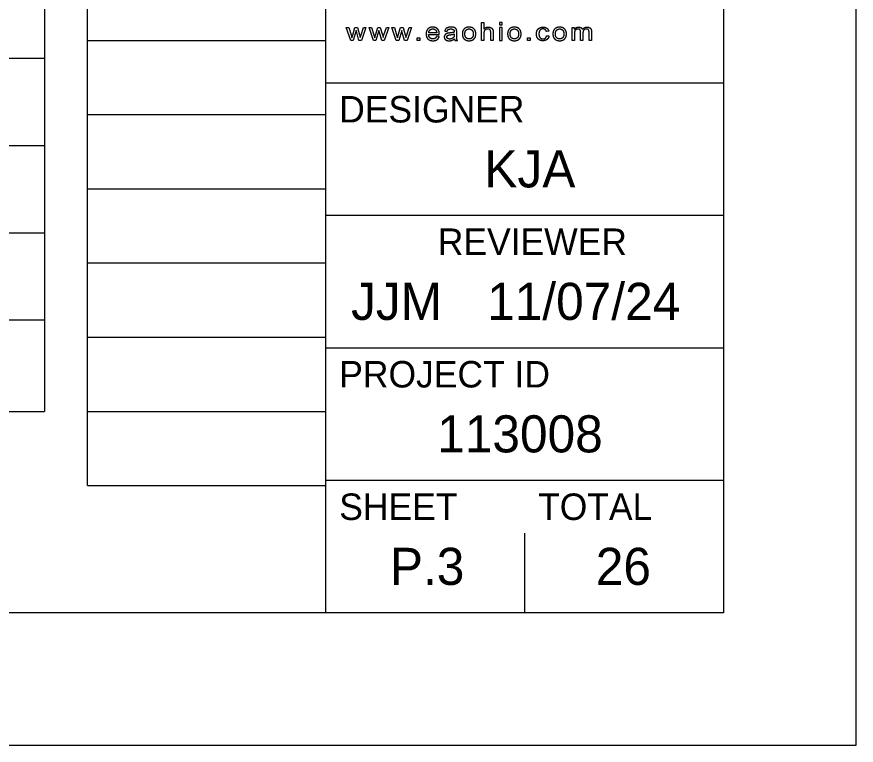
# Model space of a CAD drawing. Extents: x 0 to 34, y 0 to 22.
# Drawn here: x 30.834 to 34, y 0 to 2.749 of the extents above; entities that cross this region are included whole.
import ezdxf

# ---------------------------------------------------------------- set-up
doc = ezdxf.new("R2010")
doc.units = 0
for name, color, linetype in [('SH_Border', 7, 'Continuous'), ('SH_Cut_Line', 7, 'Continuous'), ('SH_Data', 7, 'Continuous'), ('TX_X_20', 7, 'Continuous')]:
    doc.layers.add(name, color=color, linetype=linetype)

msp = doc.modelspace()

# ---------------------------------------------------------------- linework, layer by layer
at = {"layer": 'SH_Border'}
for p, q in [((32, 0.5), (32, 21.5)), ((32, 2.5), (33.5, 2.5)), ((32, 2), (33.5, 2)), ((32, 1.5), (33.5, 1.5)), ((32, 1), (33.5, 1))]:
    msp.add_line(p, q, dxfattribs=at)
msp.add_lwpolyline([(1.5, 21.5), (33.5, 21.5), (33.5, 0.5), (1.5, 0.5)], close=True, dxfattribs=at)
at = {"layer": 'SH_Cut_Line'}
msp.add_lwpolyline([(0, 0), (34, 0), (34, 22), (0, 22)], close=True, dxfattribs=at)
at = {"layer": 'SH_Data'}
for p, q in [((31.1, 0.98), (31.1, 21.14)), ((32, 0.98), (32, 21.14)), ((30.9386, 5.2448), (30.9386, 1.2589)), ((31.1, 2.66), (32, 2.66)), ((20.5456, 2.593), (30.9386, 2.593)), ((31.1, 2.38), (32, 2.38)), ((20.5456, 2.2636), (30.9386, 2.2636)), ((31.1, 2.1), (32, 2.1)), ((20.5456, 1.9342), (30.9386, 1.9342)), ((31.1, 1.82), (32, 1.82)), ((20.5456, 1.6048), (30.9386, 1.6048)), ((31.1, 1.54), (32, 1.54)), ((20.5456, 1.2589), (30.9386, 1.2589)), ((31.1, 1.26), (32, 1.26)), ((31.1, 0.98), (32, 0.98)), ((32.75, 0.5), (32.75, 0.8)), ((32.375, 0.675), (32.375, 0.675))]:
    msp.add_line(p, q, dxfattribs=at)
at = {"layer": 'TX_X_20'}
for p, q in [((32.4477, 2.6948), (32.4567, 2.6937)), ((32.4931, 2.6802), (32.4931, 2.6913)), ((32.8402, 2.6944), (32.8313, 2.6931)), ((32.387, 2.6821), (32.4274, 2.6821)), ((32.4178, 2.6889), (32.3875, 2.6889)), ((32.4272, 2.6744), (32.4177, 2.6755)), ((32.4838, 2.6843), (32.4838, 2.6812)), ((32.4846, 2.6656), (32.4846, 2.6656)), ((32.5143, 2.6842), (32.5143, 2.6842)), ((32.5238, 2.6842), (32.5238, 2.6842)), ((32.6852, 2.6842), (32.6852, 2.6842)), ((32.6946, 2.6842), (32.6946, 2.6842)), ((32.8321, 2.6776), (32.8411, 2.6765)), ((32.856, 2.6842), (32.856, 2.6842)), ((32.8655, 2.6842), (32.8655, 2.6842)), ((32.4864, 2.6596), (32.496, 2.6596))]:
    msp.add_line(p, q, dxfattribs=at)
for points in [[(32.5955, 2.6865), (32.5955, 2.6596), (32.5863, 2.6596), (32.5863, 2.7276), (32.5955, 2.7276), (32.5955, 2.7032)], [(32.1007, 2.68), (32.1093, 2.7089), (32.1188, 2.7089), (32.1269, 2.6802), (32.1295, 2.6708), (32.1327, 2.6804), (32.142, 2.7089), (32.1509, 2.7089), (32.1339, 2.6596), (32.1244, 2.6596), (32.1158, 2.6891), (32.1137, 2.6975), (32.1027, 2.6596), (32.0931, 2.6596), (32.0766, 2.7089), (32.0861, 2.7089), (32.0947, 2.6804), (32.0979, 2.6698)], [(32.1867, 2.68), (32.1953, 2.7089), (32.2048, 2.7089), (32.2129, 2.6802), (32.2155, 2.6708), (32.2186, 2.6804), (32.228, 2.7089), (32.2369, 2.7089), (32.2199, 2.6596), (32.2104, 2.6596), (32.2018, 2.6891), (32.1997, 2.6975), (32.1886, 2.6596), (32.179, 2.6596), (32.1625, 2.7089), (32.172, 2.7089), (32.1807, 2.6804), (32.1838, 2.6698)], [(32.2726, 2.68), (32.2813, 2.7089), (32.2907, 2.7089), (32.2988, 2.6802), (32.3015, 2.6708), (32.3046, 2.6804), (32.3139, 2.7089), (32.3229, 2.7089), (32.3059, 2.6596), (32.2964, 2.6596), (32.2878, 2.6891), (32.2856, 2.6975), (32.2746, 2.6596), (32.265, 2.6596), (32.2485, 2.7089), (32.258, 2.7089), (32.2666, 2.6804), (32.2698, 2.6698)], [(32.9372, 2.6851), (32.9372, 2.6596), (32.928, 2.6596), (32.928, 2.7089), (32.9362, 2.7089), (32.9362, 2.7019)], [(32.9694, 2.6882), (32.9694, 2.6596), (32.9602, 2.6596), (32.9602, 2.6916)], [(33.0015, 2.6934), (33.0015, 2.6596), (32.9923, 2.6596), (32.9923, 2.6906)], [(32.6305, 2.6908), (32.6305, 2.6596), (32.6213, 2.6596), (32.6213, 2.6908)]]:
    msp.add_lwpolyline(points, dxfattribs=at)
for points in [[(32.655, 2.718), (32.6642, 2.718), (32.6642, 2.7276), (32.655, 2.7276)], [(32.655, 2.6596), (32.6642, 2.6596), (32.6642, 2.7089), (32.655, 2.7089)], [(32.3437, 2.6596), (32.3437, 2.669), (32.3541, 2.669), (32.3541, 2.6596)], [(32.7597, 2.6596), (32.7597, 2.669), (32.7702, 2.669), (32.7702, 2.6596)]]:
    msp.add_lwpolyline(points, close=True, dxfattribs=at)
for points in [[(32.3846, 2.7031), (32.3775, 2.6962), (32.3775, 2.6838)], [(32.4028, 2.71), (32.3916, 2.71), (32.3846, 2.7031)], [(32.3875, 2.6889), (32.388, 2.6954), (32.3923, 2.6992)], [(32.3923, 2.6992), (32.3966, 2.7031), (32.4029, 2.7031)], [(32.4206, 2.7032), (32.4137, 2.71), (32.4028, 2.71)], [(32.4029, 2.7031), (32.4099, 2.7031), (32.4143, 2.6983)], [(32.4143, 2.6983), (32.4172, 2.6951), (32.4178, 2.6889)], [(32.4275, 2.6843), (32.4275, 2.6965), (32.4206, 2.7032)], [(32.4517, 2.7032), (32.4489, 2.7), (32.4477, 2.6948)], [(32.4598, 2.7082), (32.4545, 2.7065), (32.4517, 2.7032)], [(32.4567, 2.6937), (32.4581, 2.6989), (32.4612, 2.701)], [(32.4721, 2.71), (32.4651, 2.71), (32.4598, 2.7082)], [(32.4612, 2.701), (32.4643, 2.7031), (32.4708, 2.7031)], [(32.4708, 2.7031), (32.4777, 2.7031), (32.4812, 2.7002)], [(32.4834, 2.7085), (32.479, 2.71), (32.4721, 2.71)], [(32.4812, 2.7002), (32.4838, 2.6981), (32.4838, 2.693)], [(32.4897, 2.7047), (32.4877, 2.707), (32.4834, 2.7085)], [(32.4838, 2.693), (32.4838, 2.6925), (32.4838, 2.6908)], [(32.4926, 2.699), (32.4918, 2.7025), (32.4897, 2.7047)], [(32.4931, 2.6913), (32.4931, 2.6969), (32.4926, 2.699)], [(32.5227, 2.7045), (32.5143, 2.6979), (32.5143, 2.6842)], [(32.5398, 2.71), (32.5297, 2.71), (32.5227, 2.7045)], [(32.5238, 2.6842), (32.5238, 2.6937), (32.5283, 2.6984)], [(32.5283, 2.6984), (32.5329, 2.7031), (32.5398, 2.7031)], [(32.558, 2.7033), (32.5509, 2.71), (32.5398, 2.71)], [(32.5398, 2.7031), (32.5465, 2.7031), (32.5511, 2.6983)], [(32.5511, 2.6983), (32.5556, 2.6936), (32.5556, 2.6845)], [(32.5651, 2.6849), (32.5651, 2.6966), (32.558, 2.7033)], [(32.5955, 2.7032), (32.602, 2.71), (32.6118, 2.71)], [(32.5971, 2.6956), (32.5955, 2.6923), (32.5955, 2.6865)], [(32.6022, 2.7008), (32.5986, 2.6989), (32.5971, 2.6956)], [(32.6099, 2.7028), (32.6058, 2.7028), (32.6022, 2.7008)], [(32.6183, 2.6999), (32.6153, 2.7028), (32.6099, 2.7028)], [(32.6118, 2.71), (32.6178, 2.71), (32.6222, 2.7078)], [(32.6213, 2.6908), (32.6213, 2.697), (32.6183, 2.6999)], [(32.6222, 2.7078), (32.6267, 2.7056), (32.6286, 2.7018)], [(32.6286, 2.7018), (32.6305, 2.698), (32.6305, 2.6908)], [(32.6935, 2.7045), (32.6852, 2.6979), (32.6852, 2.6842)], [(32.7106, 2.71), (32.7005, 2.71), (32.6935, 2.7045)], [(32.6946, 2.6842), (32.6946, 2.6937), (32.6992, 2.6984)], [(32.6992, 2.6984), (32.7037, 2.7031), (32.7106, 2.7031)], [(32.7288, 2.7033), (32.7218, 2.71), (32.7106, 2.71)], [(32.7106, 2.7031), (32.7174, 2.7031), (32.7219, 2.6983)], [(32.7219, 2.6983), (32.7265, 2.6936), (32.7265, 2.6845)], [(32.7359, 2.6849), (32.7359, 2.6966), (32.7288, 2.7033)], [(32.7939, 2.684), (32.7939, 2.692), (32.7968, 2.698)], [(32.7968, 2.698), (32.7997, 2.704), (32.8056, 2.707)], [(32.8077, 2.6986), (32.8033, 2.6941), (32.8033, 2.6843)], [(32.8056, 2.707), (32.8116, 2.71), (32.8186, 2.71)], [(32.8189, 2.7031), (32.812, 2.7031), (32.8077, 2.6986)], [(32.8186, 2.71), (32.8274, 2.71), (32.833, 2.7059)], [(32.8268, 2.7006), (32.8235, 2.7031), (32.8189, 2.7031)], [(32.8313, 2.6931), (32.83, 2.6981), (32.8268, 2.7006)], [(32.833, 2.7059), (32.8387, 2.7018), (32.8402, 2.6944)], [(32.8644, 2.7045), (32.856, 2.6979), (32.856, 2.6842)], [(32.8814, 2.71), (32.8714, 2.71), (32.8644, 2.7045)], [(32.8655, 2.6842), (32.8655, 2.6937), (32.87, 2.6984)], [(32.87, 2.6984), (32.8745, 2.7031), (32.8814, 2.7031)], [(32.8997, 2.7033), (32.8926, 2.71), (32.8814, 2.71)], [(32.8814, 2.7031), (32.8882, 2.7031), (32.8927, 2.6983)], [(32.8927, 2.6983), (32.8973, 2.6936), (32.8973, 2.6845)], [(32.9068, 2.6849), (32.9068, 2.6966), (32.8997, 2.7033)], [(32.9362, 2.7019), (32.9388, 2.7055), (32.943, 2.7077)], [(32.9387, 2.6954), (32.9372, 2.6918), (32.9372, 2.6851)], [(32.9434, 2.7008), (32.9401, 2.699), (32.9387, 2.6954)], [(32.943, 2.7077), (32.9472, 2.71), (32.9527, 2.71)], [(32.9506, 2.7027), (32.9467, 2.7027), (32.9434, 2.7008)], [(32.958, 2.6999), (32.9557, 2.7027), (32.9506, 2.7027)], [(32.9527, 2.71), (32.9587, 2.71), (32.9625, 2.7077)], [(32.9602, 2.6916), (32.9602, 2.6971), (32.958, 2.6999)], [(32.9625, 2.7077), (32.9664, 2.7054), (32.968, 2.7013)], [(32.968, 2.7013), (32.9744, 2.71), (32.9847, 2.71)], [(32.9732, 2.6992), (32.9694, 2.6958), (32.9694, 2.6882)], [(32.9827, 2.7027), (32.977, 2.7027), (32.9732, 2.6992)], [(32.9882, 2.7014), (32.9858, 2.7027), (32.9827, 2.7027)], [(32.9847, 2.71), (32.9928, 2.71), (32.9972, 2.7059)], [(32.9914, 2.6978), (32.9905, 2.7), (32.9882, 2.7014)], [(32.9923, 2.6906), (32.9923, 2.6956), (32.9914, 2.6978)], [(32.9972, 2.7059), (33.0015, 2.7018), (33.0015, 2.6934)], [(32.0979, 2.6698), (32.0981, 2.6706), (32.1007, 2.68)], [(32.1838, 2.6698), (32.184, 2.6706), (32.1867, 2.68)], [(32.2698, 2.6698), (32.27, 2.6706), (32.2726, 2.68)], [(32.3775, 2.6838), (32.3775, 2.6718), (32.3845, 2.6651)], [(32.3845, 2.6651), (32.3915, 2.6585), (32.4034, 2.6585)], [(32.3921, 2.6696), (32.3875, 2.6739), (32.387, 2.6821)], [(32.4034, 2.6653), (32.3966, 2.6653), (32.3921, 2.6696)], [(32.412, 2.6677), (32.4085, 2.6653), (32.4034, 2.6653)], [(32.4034, 2.6585), (32.4128, 2.6585), (32.4189, 2.6626)], [(32.4177, 2.6755), (32.4156, 2.6702), (32.412, 2.6677)], [(32.4189, 2.6626), (32.4249, 2.6668), (32.4272, 2.6744)], [(32.4274, 2.6821), (32.4275, 2.6835), (32.4275, 2.6843)], [(32.4479, 2.6792), (32.4461, 2.6762), (32.4461, 2.6726)], [(32.4461, 2.6726), (32.4461, 2.6664), (32.4509, 2.6624)], [(32.4526, 2.684), (32.4497, 2.6822), (32.4479, 2.6792)], [(32.4509, 2.6624), (32.4556, 2.6585), (32.4646, 2.6585)], [(32.4592, 2.6867), (32.4555, 2.6858), (32.4526, 2.684)], [(32.4559, 2.6728), (32.4559, 2.675), (32.4571, 2.6768)], [(32.4586, 2.6672), (32.4559, 2.6695), (32.4559, 2.6728)], [(32.4571, 2.6768), (32.4584, 2.6785), (32.4608, 2.6795)], [(32.4668, 2.665), (32.4614, 2.665), (32.4586, 2.6672)], [(32.4674, 2.688), (32.4619, 2.6873), (32.4592, 2.6867)], [(32.4608, 2.6795), (32.4631, 2.6804), (32.4688, 2.6811)], [(32.4646, 2.6585), (32.47, 2.6585), (32.4747, 2.6601)], [(32.4762, 2.6671), (32.4721, 2.665), (32.4668, 2.665)], [(32.4838, 2.6908), (32.4785, 2.6892), (32.4674, 2.688)], [(32.4688, 2.6811), (32.4788, 2.6824), (32.4838, 2.6843)], [(32.4747, 2.6601), (32.4794, 2.6617), (32.4846, 2.6656)], [(32.4823, 2.6729), (32.4803, 2.6692), (32.4762, 2.6671)], [(32.4838, 2.6812), (32.4838, 2.6757), (32.4823, 2.6729)], [(32.4846, 2.6656), (32.485, 2.6622), (32.4864, 2.6596)], [(32.4936, 2.6655), (32.4931, 2.6686), (32.4931, 2.6802)], [(32.496, 2.6596), (32.4942, 2.6624), (32.4936, 2.6655)], [(32.5143, 2.6842), (32.5143, 2.6717), (32.5214, 2.6651)], [(32.5214, 2.6651), (32.5284, 2.6585), (32.5398, 2.6585)], [(32.5283, 2.67), (32.5238, 2.6747), (32.5238, 2.6842)], [(32.5398, 2.6653), (32.5329, 2.6653), (32.5283, 2.67)], [(32.5511, 2.6701), (32.5466, 2.6653), (32.5398, 2.6653)], [(32.5398, 2.6585), (32.5468, 2.6585), (32.5528, 2.6615)], [(32.5556, 2.6845), (32.5556, 2.6748), (32.5511, 2.6701)], [(32.5528, 2.6615), (32.5588, 2.6645), (32.562, 2.67)], [(32.562, 2.67), (32.5651, 2.6754), (32.5651, 2.6849)], [(32.6852, 2.6842), (32.6852, 2.6717), (32.6922, 2.6651)], [(32.6922, 2.6651), (32.6992, 2.6585), (32.7106, 2.6585)], [(32.6992, 2.67), (32.6946, 2.6747), (32.6946, 2.6842)], [(32.7106, 2.6653), (32.7037, 2.6653), (32.6992, 2.67)], [(32.7219, 2.6701), (32.7174, 2.6653), (32.7106, 2.6653)], [(32.7106, 2.6585), (32.7177, 2.6585), (32.7237, 2.6615)], [(32.7265, 2.6845), (32.7265, 2.6748), (32.7219, 2.6701)], [(32.7237, 2.6615), (32.7297, 2.6645), (32.7328, 2.67)], [(32.7328, 2.67), (32.7359, 2.6754), (32.7359, 2.6849)], [(32.8006, 2.6651), (32.7939, 2.6717), (32.7939, 2.684)], [(32.8185, 2.6585), (32.8074, 2.6585), (32.8006, 2.6651)], [(32.8033, 2.6843), (32.8033, 2.6743), (32.8075, 2.6698)], [(32.8075, 2.6698), (32.8117, 2.6653), (32.8185, 2.6653)], [(32.8185, 2.6653), (32.8239, 2.6653), (32.8275, 2.6683)], [(32.8335, 2.6633), (32.8274, 2.6585), (32.8185, 2.6585)], [(32.8275, 2.6683), (32.8311, 2.6713), (32.8321, 2.6776)], [(32.8411, 2.6765), (32.8396, 2.668), (32.8335, 2.6633)], [(32.856, 2.6842), (32.856, 2.6717), (32.863, 2.6651)], [(32.863, 2.6651), (32.87, 2.6585), (32.8814, 2.6585)], [(32.87, 2.67), (32.8655, 2.6747), (32.8655, 2.6842)], [(32.8814, 2.6653), (32.8745, 2.6653), (32.87, 2.67)], [(32.8928, 2.6701), (32.8882, 2.6653), (32.8814, 2.6653)], [(32.8814, 2.6585), (32.8885, 2.6585), (32.8945, 2.6615)], [(32.8973, 2.6845), (32.8973, 2.6748), (32.8928, 2.6701)], [(32.8945, 2.6615), (32.9005, 2.6645), (32.9036, 2.67)], [(32.9036, 2.67), (32.9068, 2.6754), (32.9068, 2.6849)]]:
    msp.add_open_spline(points, degree=2, dxfattribs=at)

# ---------------------------------------------------------------- texts
at = {"layer": 'SH_Data'}
for s, height, p in [('DESIGNER', 0.1, (32.05, 2.35)), ('KJA', 0.14, (32.5975, 2.105)), ('REVIEWER', 0.1, (32.4218, 1.85)), ('JJM', 0.14, (32.0946, 1.605)), ('11/07/24', 0.14, (32.6078, 1.605)), ('PROJECT ID', 0.1, (32.05, 1.35)), ('113008', 0.14, (32.4193, 1.105)), ('SHEET', 0.1, (32.05, 0.85)), ('TOTAL', 0.1, (32.8, 0.85)), ('P.3', 0.14, (32.241, 0.605)), ('26', 0.14, (33.0176, 0.605))]:
    msp.add_text(s, height=height, dxfattribs=at).set_placement(p)

doc.saveas('drawing.dxf')
